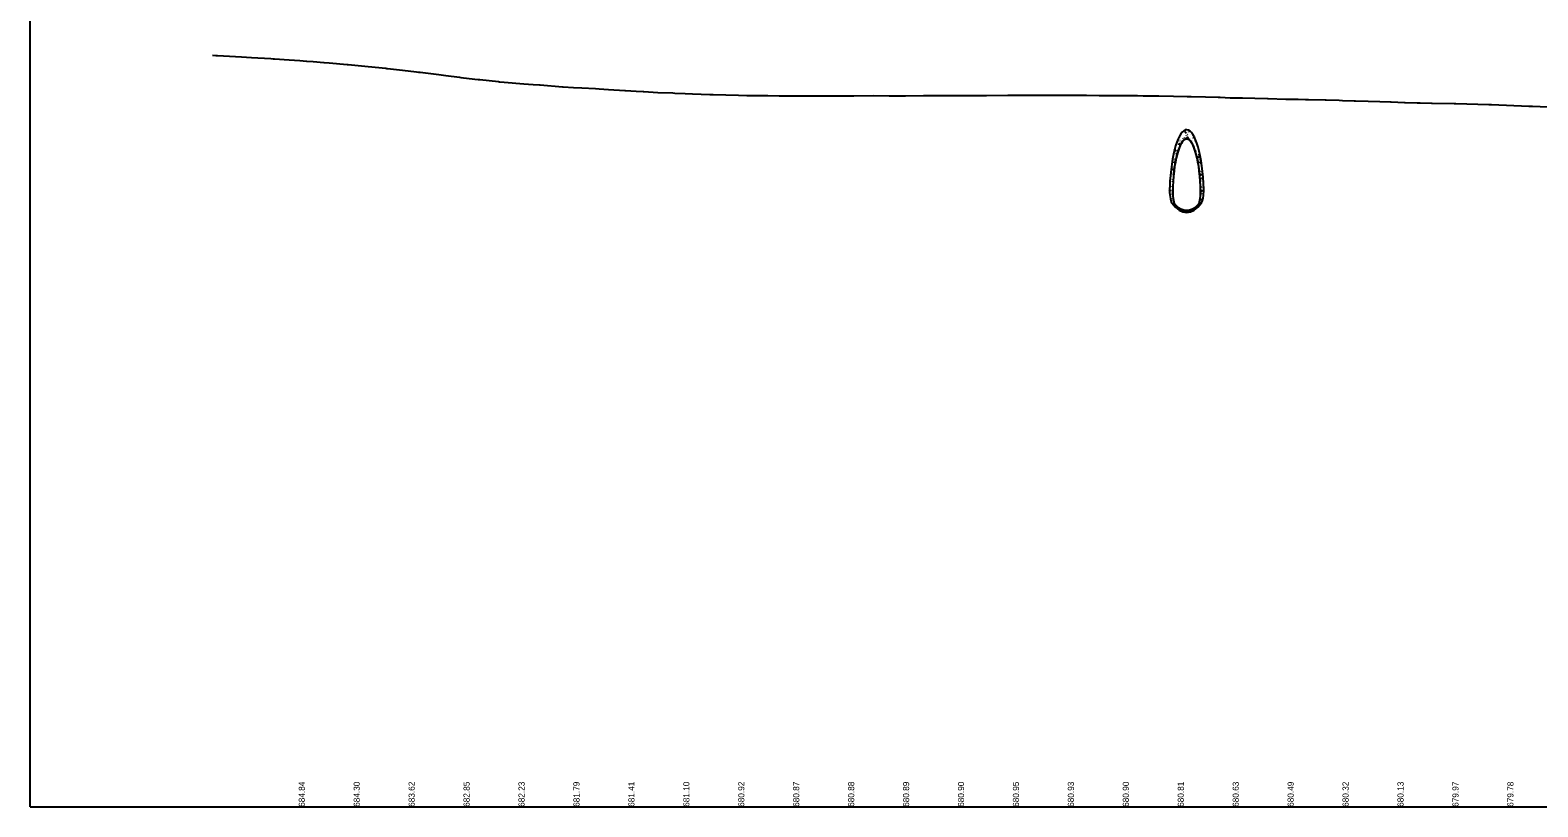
# Model space of a CAD drawing. Extents: x 153902 to 157473, y 413085 to 414252.
# Drawn here: x 156118 to 156804, y 413545 to 413898 of the extents above; entities that cross this region are included whole.
import ezdxf

# ---------------------------------------------------------------- set-up
doc = ezdxf.new("R2010")
doc.units = 0
for name, color, linetype in [('DR_X_Ditch', 7, 'Continuous'), ('GE_P_Alignment', 7, 'Continuous'), ('HY_X_Water_Edge', 7, 'Continuous'), ('PV_X_Driveway', 7, 'Continuous'), ('RW_X_Esmt_SH', 7, 'Continuous')]:
    doc.layers.add(name, color=color, linetype=linetype)

msp = doc.modelspace()

# ---------------------------------------------------------------- linework, layer by layer
at = {"layer": 'DR_X_Ditch'}
for centre, major_axis, start_param, end_param in [((156643.79, 413821.54), (0, 31.32), 4.845485, 7.692329), ((156637.52, 413825.26), (0, 6), 1.348823, 2.819829), ((156650.05, 413825.26), (0, 6), 3.463356, 4.785164), ((156643.79, 413900.44), (0, 85.24), 2.819829, 3.463356)]:
    msp.add_ellipse(centre, major_axis=major_axis, ratio=0.25, start_param=start_param, end_param=end_param, dxfattribs=at)
at = {"layer": 'GE_P_Alignment'}
for q in [(156117.51, 414047.99), (157473.02, 413544.82)]:
    msp.add_line((156117.51, 413544.82), q, dxfattribs=at)
at = {"layer": 'HY_X_Water_Edge'}
for p, q in [((156640.86, 413849.24), (156640.88, 413849.13)), ((156641.47, 413851.16), (156641.51, 413851.26)), ((156642.11, 413848.87), (156642.12, 413848.77)), ((156642.93, 413849.4), (156642.98, 413849.51)), ((156643.3, 413852.6), (156643.35, 413852.71)), ((156643.7, 413850.23), (156643.75, 413850.34)), ((156644.24, 413850.68), (156644.29, 413850.79)), ((156644.76, 413851.82), (156644.81, 413851.92)), ((156645.4, 413848.99), (156645.44, 413849.1)), ((156645.53, 413850.57), (156645.58, 413850.5)), ((156646.67, 413849.24), (156646.68, 413849.13)), ((156638.27, 413842.38), (156638.28, 413842.27)), ((156639.59, 413843.4), (156639.64, 413843.51)), ((156639.73, 413844.98), (156639.77, 413844.91)), ((156639.84, 413847.79), (156639.85, 413847.68)), ((156640.76, 413848), (156640.81, 413847.93)), ((156641.11, 413846.83), (156641.16, 413846.76)), ((156641.91, 413847.57), (156641.84, 413847.55)), ((156645.64, 413847.79), (156645.65, 413847.68)), ((156646.57, 413848), (156646.62, 413847.93)), ((156646.92, 413846.83), (156646.96, 413846.76)), ((156647.27, 413845.56), (156647.32, 413845.67)), ((156647.91, 413843.28), (156647.92, 413843.17)), ((156648.74, 413843.81), (156648.78, 413843.91)), ((156649.1, 413841.41), (156649.15, 413841.52)), ((156637.49, 413835.82), (156637.54, 413835.93)), ((156637.9, 413839.05), (156637.95, 413839.15)), ((156638.54, 413837.73), (156638.13, 413837.69)), ((156638.27, 413836.79), (156638.28, 413836.68)), ((156638.44, 413839.5), (156638.49, 413839.6)), ((156638.96, 413840.63), (156639.01, 413840.74)), ((156649.51, 413839.05), (156649.56, 413839.15)), ((156649.88, 413836.79), (156649.89, 413836.68)), ((156650.05, 413839.5), (156650.09, 413839.6)), ((156650.57, 413835.04), (156650.61, 413835.14)), ((156650.59, 413836.09), (156650.68, 413836.29)), ((156650.71, 413836.13), (156650.59, 413836.09)), ((156637.13, 413832.62), (156637.18, 413832.73)), ((156637.56, 413829.1), (156637.3, 413829.02)), ((156637.49, 413830.23), (156637.54, 413830.33)), ((156637.9, 413833.45), (156637.94, 413833.55)), ((156649.88, 413831.19), (156649.89, 413831.09)), ((156650.05, 413833.9), (156650.09, 413834.01)), ((156650.05, 413828.31), (156650.09, 413828.42)), ((156650.57, 413829.44), (156650.61, 413829.55)), ((156651.33, 413828.2), (156651.38, 413828.13)), ((156636.3, 413826.5), (156636.32, 413826.39)), ((156637.13, 413827.02), (156637.18, 413827.13)), ((156637.13, 413821.43), (156637.18, 413821.54)), ((156637.3, 413823.43), (156637.41, 413823.65)), ((156637.42, 413823.47), (156637.3, 413823.43)), ((156637.39, 413824.6), (156637.39, 413824.61)), ((156650.19, 413824.61), (156650.19, 413824.6)), ((156650.57, 413823.85), (156650.61, 413823.96)), ((156651.2, 413826.62), (156651.25, 413826.73)), ((156651.33, 413822.6), (156651.37, 413822.55)), ((156651.45, 413825.41), (156651.46, 413825.3)), ((156637.49, 413819.04), (156637.54, 413819.15)), ((156638.51, 413818.66), (156638.6, 413818.58)), ((156638.96, 413818.26), (156638.96, 413818.26)), ((156639.73, 413817.01), (156639.77, 413816.94)), ((156642.93, 413815.84), (156642.98, 413815.94)), ((156645.4, 413815.45), (156645.44, 413815.54)), ((156649.09, 413817.89), (156648.91, 413817.83)), ((156648.98, 413818.58), (156649.06, 413818.66)), ((156649.88, 413820.01), (156649.89, 413819.9))]:
    msp.add_line(p, q, dxfattribs=at)
for points in [[(156643.1, 413851.4), (156643.24, 413851.69), (156643.48, 413851.51), (156643.1, 413851.4)], [(156643.93, 413848.88), (156644.25, 413849.49), (156644.49, 413848.93), (156643.94, 413848.88)], [(156638.25, 413843.54), (156638.44, 413843.89), (156638.69, 413843.34), (156638.2, 413843.29)], [(156638.98, 413841.68), (156639.12, 413841.98), (156639.36, 413841.8), (156638.98, 413841.68)], [(156640.27, 413845.94), (156640.37, 413846.61), (156640.79, 413846.17), (156640.28, 413845.94)], [(156641.84, 413847.55), (156641.98, 413847.84), (156642.08, 413847.77)], [(156646.48, 413846.29), (156646.59, 413846.17), (156646.55, 413846.16)], [(156647.64, 413847.55), (156647.78, 413847.84), (156648.02, 413847.67), (156647.64, 413847.55)], [(156637.3, 413834.62), (156637.44, 413834.91), (156637.68, 413834.73), (156637.3, 413834.62)], [(156637.56, 413840.42), (156637.68, 413840.33), (156637.53, 413840.28)], [(156638.12, 413837.69), (156638.44, 413838.3), (156638.59, 413837.97)], [(156648.91, 413840.21), (156649.05, 413840.5), (156649.28, 413840.33), (156648.91, 413840.21)], [(156649.73, 413837.69), (156650.05, 413838.3), (156650.3, 413837.74), (156649.74, 413837.69)], [(156636.33, 413830.95), (156636.41, 413830.88), (156636.33, 413830.86)], [(156637.3, 413829.02), (156637.44, 413829.32), (156637.57, 413829.22)], [(156649.76, 413832.16), (156650.05, 413832.7), (156650.3, 413832.15), (156649.76, 413832.1)], [(156650.59, 413830.5), (156650.73, 413830.79), (156650.96, 413830.61), (156650.59, 413830.5)], [(156636.03, 413825.17), (156636.18, 413825.47), (156636.41, 413825.29), (156636.03, 413825.17)], [(156649.95, 413821.32), (156650.05, 413821.52), (156650.3, 413820.96), (156649.88, 413820.93)], [(156650.1, 413827), (156650.3, 413826.55), (156650.12, 413826.54)], [(156650.59, 413824.9), (156650.73, 413825.2), (156650.96, 413825.02), (156650.59, 413824.9)], [(156643.93, 413815.32), (156644.25, 413815.92), (156644.49, 413815.37), (156643.94, 413815.32)], [(156648.91, 413817.83), (156649.05, 413818.13), (156649.2, 413818.01)]]:
    msp.add_lwpolyline(points, dxfattribs=at)
at = {"layer": 'PV_X_Driveway'}
msp.add_line((156637.43, 413824.6), (156637.43, 413824.6), dxfattribs=at)
for centre, major_axis, start_param, end_param in [((156643.79, 413823.05), (0, 25.65), 4.773128, 7.793243), ((156643.79, 413823.05), (0, 25.48), 4.773128, 7.793243), ((156638.93, 413824.6), (0, 6.17), 1.570796, 2.924119), ((156638.93, 413824.6), (0, 6), 1.570796, 2.924119), ((156648.65, 413824.6), (0, 6), 3.359067, 4.712389), ((156648.65, 413824.6), (0, 6.17), 3.359067, 4.712389), ((156643.79, 413902), (0, 85.97), 2.893611, 3.389574), ((156643.79, 413902), (0, 85.8), 2.893611, 3.389574)]:
    msp.add_ellipse(centre, major_axis=major_axis, ratio=0.25, start_param=start_param, end_param=end_param, dxfattribs=at)
at = {"layer": 'RW_X_Esmt_SH'}
msp.add_lwpolyline([(156200.48, 413886.73), (156201.95, 413886.67), (156202.7, 413886.62), (156213.75, 413886.09), (156218.31, 413885.8), (156227.01, 413885.28), (156228.07, 413885.2), (156228.64, 413885.16), (156235.42, 413884.67), (156240.28, 413884.35), (156243.33, 413884.1), (156243.43, 413884.09), (156246.23, 413883.87), (156251.22, 413883.46), (156251.32, 413883.45), (156253.55, 413883.27), (156261.71, 413882.56), (156261.93, 413882.53), (156262.24, 413882.49), (156266.82, 413882.08), (156271.28, 413881.66), (156279.3, 413880.86), (156279.83, 413880.79), (156280.09, 413880.76), (156287.02, 413880), (156293.36, 413879.2), (156294.3, 413879.08), (156294.97, 413878.99), (156303.47, 413877.93), (156306.63, 413877.53), (156312.86, 413876.75), (156313.53, 413876.64), (156319.9, 413875.94), (156321.44, 413875.77), (156322.09, 413875.69), (156330.59, 413874.78), (156331.06, 413874.73), (156333.16, 413874.54), (156342.19, 413873.75), (156346.43, 413873.51), (156349.32, 413873.36), (156349.58, 413873.35), (156359.7, 413872.44), (156359.95, 413872.42), (156360.01, 413872.42), (156364.74, 413872.13), (156368.58, 413871.9), (156368.63, 413871.89), (156374.83, 413871.61), (156376.48, 413871.5), (156380.75, 413871.17), (156388.09, 413870.7), (156388.42, 413870.68), (156393.25, 413870.42), (156396.5, 413870.23), (156396.72, 413870.21), (156403.13, 413869.84), (156410.03, 413869.59), (156410.88, 413869.55), (156410.89, 413869.55), (156415.54, 413869.33), (156418.92, 413869.17), (156418.92, 413869.17), (156426.81, 413868.89), (156428.24, 413868.83), (156428.29, 413868.83), (156439.78, 413868.54), (156439.86, 413868.54), (156443.58, 413868.5), (156450.11, 413868.43), (156450.12, 413868.43), (156453.15, 413868.4), (156458.41, 413868.35), (156459.68, 413868.34), (156460.36, 413868.34), (156466.25, 413868.31), (156466.33, 413868.3), (156471.98, 413868.34), (156476.22, 413868.35), (156478.27, 413868.35), (156478.29, 413868.35), (156479.54, 413868.35), (156484.61, 413868.34), (156492.27, 413868.35), (156492.38, 413868.34), (156501.31, 413868.39), (156508.39, 413868.36), (156508.49, 413868.36), (156514.4, 413868.36), (156515.82, 413868.35), (156524.07, 413868.43), (156525.59, 413868.45), (156525.79, 413868.45), (156542.08, 413868.41), (156542.23, 413868.41), (156544.05, 413868.42), (156552.5, 413868.46), (156552.77, 413868.47), (156562.38, 413868.6), (156562.72, 413868.61), (156564.03, 413868.61), (156572.85, 413868.65), (156573.07, 413868.65), (156580.98, 413868.66), (156584.01, 413868.61), (156589, 413868.54), (156589.13, 413868.54), (156598.28, 413868.54), (156603.99, 413868.51), (156606.92, 413868.48), (156607.35, 413868.48), (156611.61, 413868.43), (156612.36, 413868.43), (156612.49, 413868.43), (156617.08, 413868.41), (156621.4, 413868.39), (156621.41, 413868.39), (156623.97, 413868.35), (156626.35, 413868.3), (156631.06, 413868.22), (156631.15, 413868.22), (156637.81, 413868.15), (156637.87, 413868.15), (156643.95, 413868.02), (156645.81, 413867.97), (156652.32, 413867.77), (156652.37, 413867.77), (156658.15, 413867.68), (156659.04, 413867.64), (156663.64, 413867.42), (156663.93, 413867.42), (156669.13, 413867.32), (156669.23, 413867.31), (156674.83, 413867.16), (156680.55, 413867.02), (156680.8, 413867.01), (156680.87, 413867.01), (156688.89, 413866.85), (156694.32, 413866.75), (156694.6, 413866.74), (156697.81, 413866.69), (156699.24, 413866.65), (156706.85, 413866.44), (156707.35, 413866.44), (156713.25, 413866.26), (156714.75, 413866.21), (156720.02, 413866.01), (156720.6, 413866), (156726.39, 413865.84), (156731.69, 413865.71), (156736.52, 413865.55), (156736.86, 413865.54), (156742.91, 413865.33), (156743.16, 413865.32), (156748.63, 413865.17), (156750.1, 413865.12), (156755.23, 413865.01), (156755.57, 413865), (156765.57, 413864.75), (156766.03, 413864.73), (156766.27, 413864.73), (156781.27, 413864.35), (156781.48, 413864.34), (156782.52, 413864.31), (156799.46, 413863.65), (156800.59, 413863.6), (156800.84, 413863.59), (156801.11, 413863.58), (156815.27, 413862.93)], dxfattribs=at)

# ---------------------------------------------------------------- texts
at = {"layer": 'HY_X_Water_Edge'}
for s, p in [('684.84', (156242.51, 413544.82)), ('684.30', (156267.51, 413544.82)), ('683.62', (156292.51, 413544.82)), ('682.85', (156317.51, 413544.82)), ('682.23', (156342.51, 413544.82)), ('681.79', (156367.51, 413544.82)), ('681.41', (156392.51, 413544.82)), ('681.10', (156417.51, 413544.82)), ('680.92', (156442.51, 413544.82)), ('680.87', (156467.51, 413544.82)), ('680.88', (156492.51, 413544.82)), ('680.89', (156517.51, 413544.82)), ('680.90', (156542.51, 413544.82)), ('680.95', (156567.51, 413544.82)), ('680.93', (156592.51, 413544.82)), ('680.90', (156617.51, 413544.82)), ('680.81', (156642.51, 413544.82)), ('680.63', (156667.51, 413544.82)), ('680.49', (156692.51, 413544.82)), ('680.32', (156717.51, 413544.82)), ('680.13', (156742.51, 413544.82)), ('679.97', (156767.51, 413544.82)), ('679.78', (156792.51, 413544.82))]:
    msp.add_text(s, height=2.8, rotation=90, dxfattribs=at).set_placement(p)

doc.saveas('drawing.dxf')
